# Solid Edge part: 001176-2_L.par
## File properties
Last saved by: morva
Revision: 82
Accuracy: 0.990
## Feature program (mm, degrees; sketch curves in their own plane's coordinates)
body "unnamed Body 1"
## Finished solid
Body 1: solid body, 81 faces, 245 edges, 172 vertices.
  Faces by surface: cylinder 38, plane 19, spline 13, torus 6, spun 4, swept 1
  Edges by curve: curve on surface 173, line 57, spline 13, circle 2
Bounding box of the edges (mm; curved faces can reach further): 87.727 x 35.570 x 98.744, from (501.9653, 396.993, -168.4042) to (589.6926, 432.5628, -69.6602).
Cylindrical faces by radius (mm): R0.75 x2, R1 x2, R1.0004 x1, R1.5 x2, R2 x5, R2.5 x2, R3.5 x4, R4.1256 x1, R4.4184 x1, R5.5 x4, R7.5 x1, R9 x1, R10 x3, R12 x2, R15.2628 x2, R41.0833 x2, R158.12 x2, R1237.1852 x1
Toroidal faces (ring radius, tube radius in mm): R10.9893 r1.0001 x2, R157.2371 r1 x2, R1236.1852 r1 x2
Planar faces by outward normal: oblique 19
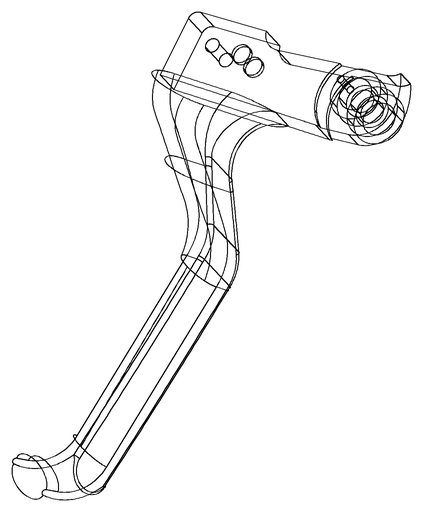
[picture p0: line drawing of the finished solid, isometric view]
